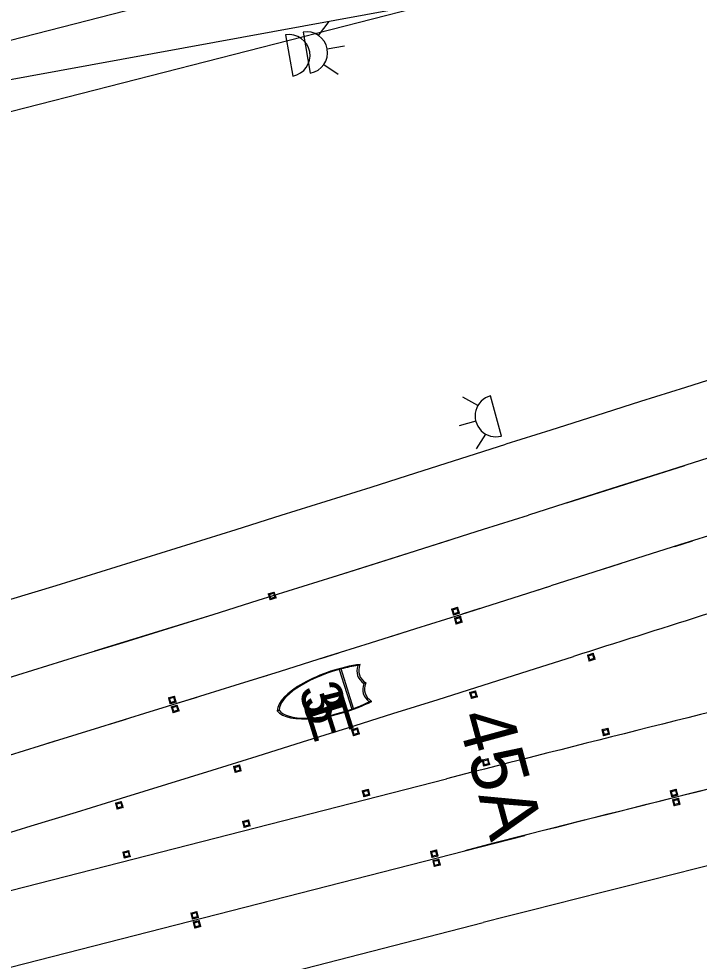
# Model space of a CAD drawing. Extents: x 2471014 to 2497726, y 6959577 to 6980268.
# Drawn here: x 2486252 to 2486362, y 6968251.5 to 6968403.9 of the extents above; entities that cross this region are included whole.
import ezdxf

# ---------------------------------------------------------------- set-up
doc = ezdxf.new("R2010")
doc.units = 0
for name, color, linetype in [('1', 7, 'Continuous'), ('13', 7, 'Continuous'), ('18', 7, 'Continuous'), ('23', 7, 'Continuous'), ('25', 7, 'Continuous'), ('5', 7, 'Continuous'), ('59', 7, 'Continuous'), ('C-ANNO-NOTE', 7, 'Continuous'), ('Level 40', 7, 'Continuous'), ('PMK_Del_D-SY_SZ_TYC_CTB', 7, 'Continuous'), ('PMK_Pav_Mark_Multi_Shield', 7, 'Continuous'), ('PMK_Pav_Mark_Wht_Number', 7, 'Continuous'), ('RDWY_PAVE_XSTREET_FOC', 7, 'Continuous'), ('S-BRDG-BENT', 7, 'Continuous'), ('SHADE SW', 7, 'Continuous'), ('V7_25', 7, 'Continuous')]:
    doc.layers.add(name, color=color, linetype=linetype)

msp = doc.modelspace()

# ---------------------------------------------------------------- linework, layer by layer
at = {"layer": '1'}
msp.add_line((2486324.14, 6968269.39), (2486333.83, 6968271.87), dxfattribs=at)
at = {"layer": '13'}
msp.add_line((2486190.43, 6968383.05), (2486361.16, 6968414.31), dxfattribs=at)
for centre, start, end in [((2488909.95, 6960235.84), 104.374936, 107.663843), ((2483751.61, 6976434.35), 284.374936, 287.663843)]:
    msp.add_arc(centre, 8500, start, end, dxfattribs=at)
at = {"layer": '18'}
msp.add_line((2485876.76, 6968142.35), (2486327.12, 6968257.77), dxfattribs=at)
msp.add_arc((2487750.43, 6962704.26), 5733, 101.840567, 104.374936, dxfattribs=at)
at = {"layer": '23'}
for p, q in [((2486292.36, 6968310.91), (2486293.33, 6968311.21)), ((2486292.57, 6968310.81), (2486292.36, 6968310.91)), ((2486292.36, 6968310.91), (2486292.44, 6968310.65)), ((2486292.44, 6968310.65), (2486292.66, 6968309.94)), ((2486292.77, 6968310.16), (2486292.57, 6968310.81)), ((2486293.33, 6968311.21), (2486293.21, 6968311.01)), ((2486293.21, 6968311.01), (2486293.26, 6968310.87)), ((2486293.26, 6968310.87), (2486293.42, 6968310.36)), ((2486293.63, 6968310.25), (2486293.33, 6968311.21)), ((2486293.63, 6968310.25), (2486292.66, 6968309.94)), ((2486292.66, 6968309.94), (2486292.77, 6968310.16)), ((2486293.42, 6968310.36), (2486293.63, 6968310.25)), ((2486322, 6968308.44), (2486322.97, 6968308.75)), ((2486322.21, 6968308.34), (2486322, 6968308.44)), ((2486322, 6968308.44), (2486322.08, 6968308.18)), ((2486322.08, 6968308.18), (2486322.31, 6968307.47)), ((2486322.41, 6968307.69), (2486322.21, 6968308.34)), ((2486323.27, 6968307.78), (2486322.31, 6968307.47)), ((2486322.31, 6968307.47), (2486322.41, 6968307.69)), ((2486322.97, 6968308.75), (2486322.86, 6968308.54)), ((2486322.86, 6968308.54), (2486322.9, 6968308.41)), ((2486322.9, 6968308.41), (2486323.06, 6968307.9)), ((2486323.27, 6968307.78), (2486322.97, 6968308.75)), ((2486323.06, 6968307.9), (2486323.27, 6968307.78)), ((2486322.46, 6968307), (2486323.43, 6968307.31)), ((2486322.67, 6968306.9), (2486322.46, 6968307)), ((2486322.46, 6968307), (2486322.55, 6968306.74)), ((2486322.55, 6968306.74), (2486322.77, 6968306.03)), ((2486322.88, 6968306.25), (2486322.67, 6968306.9)), ((2486323.74, 6968306.34), (2486322.77, 6968306.03)), ((2486322.77, 6968306.03), (2486322.88, 6968306.25)), ((2486323.43, 6968307.31), (2486323.32, 6968307.1)), ((2486323.32, 6968307.1), (2486323.36, 6968306.97)), ((2486323.36, 6968306.97), (2486323.52, 6968306.46)), ((2486323.74, 6968306.34), (2486323.43, 6968307.31)), ((2486323.52, 6968306.46), (2486323.74, 6968306.34)), ((2486343.96, 6968301), (2486344.92, 6968301.31)), ((2486344.17, 6968300.89), (2486343.96, 6968301)), ((2486343.96, 6968301), (2486344.26, 6968300.04)), ((2486344.33, 6968300.38), (2486344.17, 6968300.89)), ((2486345.23, 6968300.35), (2486344.26, 6968300.04)), ((2486344.26, 6968300.04), (2486344.38, 6968300.24)), ((2486344.38, 6968300.24), (2486344.33, 6968300.38)), ((2486344.92, 6968301.31), (2486344.82, 6968301.09)), ((2486344.82, 6968301.09), (2486345.02, 6968300.45)), ((2486345.15, 6968300.6), (2486344.92, 6968301.31)), ((2486345.02, 6968300.45), (2486345.23, 6968300.35)), ((2486345.23, 6968300.35), (2486345.15, 6968300.6)), ((2486324.89, 6968294.95), (2486325.86, 6968295.26)), ((2486325.86, 6968295.26), (2486325.75, 6968295.04)), ((2486326.09, 6968294.55), (2486325.86, 6968295.26)), ((2486276.2, 6968294.09), (2486277.17, 6968294.39)), ((2486276.41, 6968293.99), (2486276.2, 6968294.09)), ((2486276.2, 6968294.09), (2486276.28, 6968293.84)), ((2486276.28, 6968293.84), (2486276.5, 6968293.12)), ((2486276.61, 6968293.34), (2486276.41, 6968293.99)), ((2486277.17, 6968294.39), (2486277.05, 6968294.19)), ((2486277.05, 6968294.19), (2486277.1, 6968294.06)), ((2486277.1, 6968294.06), (2486277.25, 6968293.54)), ((2486277.47, 6968293.43), (2486277.17, 6968294.39)), ((2486325.11, 6968294.84), (2486324.89, 6968294.95)), ((2486324.89, 6968294.95), (2486325.2, 6968293.99)), ((2486325.27, 6968294.32), (2486325.11, 6968294.84)), ((2486326.17, 6968294.29), (2486325.2, 6968293.99)), ((2486325.2, 6968293.99), (2486325.31, 6968294.19)), ((2486325.31, 6968294.19), (2486325.27, 6968294.32)), ((2486325.75, 6968295.04), (2486325.96, 6968294.39)), ((2486325.96, 6968294.39), (2486326.17, 6968294.29)), ((2486326.17, 6968294.29), (2486326.09, 6968294.55)), ((2486277.47, 6968293.43), (2486276.5, 6968293.12)), ((2486276.5, 6968293.12), (2486276.61, 6968293.34)), ((2486276.66, 6968292.65), (2486277.63, 6968292.95)), ((2486276.87, 6968292.55), (2486276.66, 6968292.65)), ((2486276.66, 6968292.65), (2486276.74, 6968292.4)), ((2486276.74, 6968292.4), (2486276.96, 6968291.68)), ((2486277.07, 6968291.9), (2486276.87, 6968292.55)), ((2486277.25, 6968293.54), (2486277.47, 6968293.43)), ((2486277.63, 6968292.95), (2486277.52, 6968292.75)), ((2486277.52, 6968292.75), (2486277.56, 6968292.62)), ((2486277.56, 6968292.62), (2486277.72, 6968292.1)), ((2486277.93, 6968291.99), (2486277.63, 6968292.95)), ((2486277.93, 6968291.99), (2486276.96, 6968291.68)), ((2486276.96, 6968291.68), (2486277.07, 6968291.9)), ((2486277.72, 6968292.1), (2486277.93, 6968291.99)), ((2486305.82, 6968288.95), (2486306.79, 6968289.25)), ((2486306.79, 6968289.25), (2486306.68, 6968289.03)), ((2486307.01, 6968288.54), (2486306.79, 6968289.25)), ((2486346.33, 6968288.97), (2486347.31, 6968289.22)), ((2486347.31, 6968289.22), (2486347.19, 6968289)), ((2486347.49, 6968288.49), (2486347.31, 6968289.22)), ((2486306.03, 6968288.83), (2486305.82, 6968288.95)), ((2486305.82, 6968288.95), (2486306.12, 6968287.98)), ((2486306.19, 6968288.32), (2486306.03, 6968288.83)), ((2486307.09, 6968288.28), (2486306.12, 6968287.98)), ((2486306.12, 6968287.98), (2486306.24, 6968288.18)), ((2486306.24, 6968288.18), (2486306.19, 6968288.32)), ((2486306.68, 6968289.03), (2486306.88, 6968288.39)), ((2486306.88, 6968288.39), (2486307.09, 6968288.28)), ((2486307.09, 6968288.28), (2486307.01, 6968288.54)), ((2486346.53, 6968288.84), (2486346.33, 6968288.97)), ((2486346.33, 6968288.97), (2486346.57, 6968287.99)), ((2486346.67, 6968288.32), (2486346.53, 6968288.84)), ((2486347.56, 6968288.23), (2486346.57, 6968287.99)), ((2486346.57, 6968287.99), (2486346.7, 6968288.18)), ((2486346.7, 6968288.18), (2486346.67, 6968288.32)), ((2486347.19, 6968289), (2486347.36, 6968288.35)), ((2486347.36, 6968288.35), (2486347.56, 6968288.23)), ((2486347.56, 6968288.23), (2486347.49, 6968288.49)), ((2486286.73, 6968282.99), (2486287.7, 6968283.29)), ((2486287.7, 6968283.29), (2486287.59, 6968283.07)), ((2486287.59, 6968283.07), (2486287.79, 6968282.42)), ((2486287.92, 6968282.58), (2486287.7, 6968283.29)), ((2486326.94, 6968284.06), (2486327.92, 6968284.31)), ((2486327.15, 6968283.93), (2486326.94, 6968284.06)), ((2486326.94, 6968284.06), (2486327.19, 6968283.08)), ((2486327.28, 6968283.41), (2486327.15, 6968283.93)), ((2486328.17, 6968283.33), (2486327.19, 6968283.08)), ((2486327.19, 6968283.08), (2486327.31, 6968283.27)), ((2486327.31, 6968283.27), (2486327.28, 6968283.41)), ((2486327.92, 6968284.31), (2486327.8, 6968284.1)), ((2486327.8, 6968284.1), (2486327.97, 6968283.44)), ((2486328.1, 6968283.59), (2486327.92, 6968284.31)), ((2486327.97, 6968283.44), (2486328.17, 6968283.33)), ((2486328.17, 6968283.33), (2486328.1, 6968283.59)), ((2486286.94, 6968282.87), (2486286.73, 6968282.99)), ((2486286.73, 6968282.99), (2486287.03, 6968282.02)), ((2486287.1, 6968282.36), (2486286.94, 6968282.87)), ((2486288, 6968282.32), (2486287.03, 6968282.02)), ((2486287.03, 6968282.02), (2486287.14, 6968282.22)), ((2486287.14, 6968282.22), (2486287.1, 6968282.36)), ((2486287.79, 6968282.42), (2486288, 6968282.32)), ((2486288, 6968282.32), (2486287.92, 6968282.58)), ((2486307.56, 6968279.1), (2486308.55, 6968279.35)), ((2486307.77, 6968278.97), (2486307.56, 6968279.1)), ((2486307.56, 6968279.1), (2486307.81, 6968278.11)), ((2486307.9, 6968278.45), (2486307.77, 6968278.97)), ((2486308.55, 6968279.35), (2486308.43, 6968279.13)), ((2486308.43, 6968279.13), (2486308.6, 6968278.48)), ((2486308.73, 6968278.63), (2486308.55, 6968279.35)), ((2486308.8, 6968278.37), (2486308.73, 6968278.63)), ((2486357.36, 6968279.09), (2486358.34, 6968279.33)), ((2486357.56, 6968278.97), (2486357.36, 6968279.09)), ((2486357.36, 6968279.09), (2486357.42, 6968278.82)), ((2486357.42, 6968278.82), (2486357.6, 6968278.1)), ((2486357.72, 6968278.31), (2486357.56, 6968278.97)), ((2486358.34, 6968279.33), (2486358.22, 6968279.14)), ((2486358.22, 6968279.14), (2486358.25, 6968279)), ((2486358.25, 6968279), (2486358.38, 6968278.48)), ((2486358.59, 6968278.35), (2486358.34, 6968279.33)), ((2486267.63, 6968277.07), (2486268.59, 6968277.37)), ((2486267.84, 6968276.95), (2486267.63, 6968277.07)), ((2486267.63, 6968277.07), (2486267.92, 6968276.1)), ((2486268.59, 6968277.37), (2486268.49, 6968277.15)), ((2486268.49, 6968277.15), (2486268.69, 6968276.5)), ((2486268.81, 6968276.66), (2486268.59, 6968277.37)), ((2486308.8, 6968278.37), (2486307.81, 6968278.11)), ((2486307.81, 6968278.11), (2486307.94, 6968278.31)), ((2486307.94, 6968278.31), (2486307.9, 6968278.45)), ((2486308.6, 6968278.48), (2486308.8, 6968278.37)), ((2486358.59, 6968278.35), (2486357.6, 6968278.1)), ((2486357.6, 6968278.1), (2486357.72, 6968278.31)), ((2486357.73, 6968277.63), (2486358.72, 6968277.88)), ((2486357.93, 6968277.52), (2486357.73, 6968277.63)), ((2486357.73, 6968277.63), (2486357.8, 6968277.37)), ((2486357.8, 6968277.37), (2486357.98, 6968276.65)), ((2486358.1, 6968276.86), (2486357.93, 6968277.52)), ((2486358.38, 6968278.48), (2486358.59, 6968278.35)), ((2486358.72, 6968277.88), (2486358.59, 6968277.68)), ((2486358.59, 6968277.68), (2486358.62, 6968277.54)), ((2486358.62, 6968277.54), (2486358.75, 6968277.03)), ((2486358.96, 6968276.89), (2486358.72, 6968277.88)), ((2486358.75, 6968277.03), (2486358.96, 6968276.89)), ((2486268, 6968276.44), (2486267.84, 6968276.95)), ((2486268.89, 6968276.4), (2486267.92, 6968276.1)), ((2486267.92, 6968276.1), (2486268.04, 6968276.3)), ((2486268.04, 6968276.3), (2486268, 6968276.44)), ((2486268.69, 6968276.5), (2486268.89, 6968276.4)), ((2486268.89, 6968276.4), (2486268.81, 6968276.66)), ((2486358.96, 6968276.89), (2486357.98, 6968276.65)), ((2486357.98, 6968276.65), (2486358.1, 6968276.86)), ((2486288.19, 6968274.13), (2486289.17, 6968274.38)), ((2486288.4, 6968274), (2486288.19, 6968274.13)), ((2486288.19, 6968274.13), (2486288.44, 6968273.15)), ((2486288.53, 6968273.48), (2486288.4, 6968274)), ((2486289.17, 6968274.38), (2486289.05, 6968274.17)), ((2486289.05, 6968274.17), (2486289.22, 6968273.51)), ((2486289.36, 6968273.66), (2486289.17, 6968274.38)), ((2486289.42, 6968273.4), (2486288.44, 6968273.15)), ((2486288.44, 6968273.15), (2486288.57, 6968273.35)), ((2486288.57, 6968273.35), (2486288.53, 6968273.48)), ((2486289.22, 6968273.51), (2486289.42, 6968273.4)), ((2486289.42, 6968273.4), (2486289.36, 6968273.66)), ((2486268.82, 6968269.17), (2486269.8, 6968269.42)), ((2486269.8, 6968269.42), (2486269.68, 6968269.2)), ((2486269.98, 6968268.7), (2486269.8, 6968269.42)), ((2486318.58, 6968269.25), (2486319.57, 6968269.51)), ((2486319.57, 6968269.51), (2486319.44, 6968269.31)), ((2486319.82, 6968268.52), (2486319.57, 6968269.51)), ((2486269.02, 6968269.04), (2486268.82, 6968269.17)), ((2486268.82, 6968269.17), (2486269.07, 6968268.18)), ((2486269.16, 6968268.52), (2486269.02, 6968269.04)), ((2486270.05, 6968268.44), (2486269.07, 6968268.18)), ((2486269.07, 6968268.18), (2486269.19, 6968268.38)), ((2486269.19, 6968268.38), (2486269.16, 6968268.52)), ((2486269.68, 6968269.2), (2486269.85, 6968268.55)), ((2486269.85, 6968268.55), (2486270.05, 6968268.44)), ((2486270.05, 6968268.44), (2486269.98, 6968268.7)), ((2486318.78, 6968269.14), (2486318.58, 6968269.25)), ((2486318.58, 6968269.25), (2486318.65, 6968268.99)), ((2486318.65, 6968268.99), (2486318.83, 6968268.27)), ((2486318.95, 6968268.49), (2486318.78, 6968269.14)), ((2486319.82, 6968268.52), (2486318.83, 6968268.27)), ((2486318.83, 6968268.27), (2486318.95, 6968268.49)), ((2486318.95, 6968267.8), (2486319.94, 6968268.05)), ((2486319.44, 6968269.31), (2486319.48, 6968269.17)), ((2486319.48, 6968269.17), (2486319.61, 6968268.65)), ((2486319.61, 6968268.65), (2486319.82, 6968268.52)), ((2486319.94, 6968268.05), (2486319.81, 6968267.86)), ((2486319.81, 6968267.86), (2486319.85, 6968267.72)), ((2486320.19, 6968267.07), (2486319.94, 6968268.05)), ((2486319.16, 6968267.69), (2486318.95, 6968267.8)), ((2486318.95, 6968267.8), (2486319.02, 6968267.54)), ((2486319.02, 6968267.54), (2486319.21, 6968266.82)), ((2486319.32, 6968267.03), (2486319.16, 6968267.69)), ((2486320.19, 6968267.07), (2486319.21, 6968266.82)), ((2486319.21, 6968266.82), (2486319.32, 6968267.03)), ((2486319.85, 6968267.72), (2486319.98, 6968267.2)), ((2486319.98, 6968267.2), (2486320.19, 6968267.07)), ((2486279.83, 6968259.32), (2486280.82, 6968259.58)), ((2486280.04, 6968259.21), (2486279.83, 6968259.32)), ((2486279.83, 6968259.32), (2486279.9, 6968259.06)), ((2486279.9, 6968259.06), (2486280.09, 6968258.34)), ((2486280.2, 6968258.55), (2486280.04, 6968259.21)), ((2486280.82, 6968259.58), (2486280.69, 6968259.38)), ((2486280.69, 6968259.38), (2486280.73, 6968259.24)), ((2486280.73, 6968259.24), (2486280.86, 6968258.72)), ((2486281.07, 6968258.59), (2486280.82, 6968259.58)), ((2486280.86, 6968258.72), (2486281.07, 6968258.59)), ((2486281.07, 6968258.59), (2486280.09, 6968258.34)), ((2486280.09, 6968258.34), (2486280.2, 6968258.55)), ((2486280.21, 6968257.87), (2486281.19, 6968258.12)), ((2486280.41, 6968257.76), (2486280.21, 6968257.87)), ((2486280.21, 6968257.87), (2486280.27, 6968257.61)), ((2486280.27, 6968257.61), (2486280.46, 6968256.89)), ((2486280.58, 6968257.1), (2486280.41, 6968257.76)), ((2486281.19, 6968258.12), (2486281.06, 6968257.93)), ((2486281.06, 6968257.93), (2486281.1, 6968257.79)), ((2486281.1, 6968257.79), (2486281.23, 6968257.27)), ((2486281.44, 6968257.14), (2486281.19, 6968258.12)), ((2486281.23, 6968257.27), (2486281.44, 6968257.14)), ((2486281.44, 6968257.14), (2486280.46, 6968256.89)), ((2486280.46, 6968256.89), (2486280.58, 6968257.1))]:
    msp.add_line(p, q, dxfattribs=at)
for points in [[(2486292.57, 6968310.81), (2486293.21, 6968311.01), (2486293.42, 6968310.36), (2486292.77, 6968310.16)], [(2486322.21, 6968308.34), (2486322.86, 6968308.54), (2486323.06, 6968307.9), (2486322.41, 6968307.69)], [(2486322.67, 6968306.9), (2486323.32, 6968307.1), (2486323.52, 6968306.46), (2486322.88, 6968306.25)], [(2486345.02, 6968300.45), (2486344.38, 6968300.24), (2486344.17, 6968300.89), (2486344.82, 6968301.09)], [(2486276.41, 6968293.99), (2486277.05, 6968294.19), (2486277.25, 6968293.54), (2486276.61, 6968293.34)], [(2486325.96, 6968294.39), (2486325.31, 6968294.19), (2486325.11, 6968294.84), (2486325.75, 6968295.04)], [(2486276.87, 6968292.55), (2486277.52, 6968292.75), (2486277.72, 6968292.1), (2486277.07, 6968291.9)], [(2486306.88, 6968288.39), (2486306.24, 6968288.18), (2486306.03, 6968288.83), (2486306.68, 6968289.03)], [(2486347.36, 6968288.35), (2486346.7, 6968288.18), (2486346.53, 6968288.84), (2486347.19, 6968289)], [(2486287.79, 6968282.42), (2486287.14, 6968282.22), (2486286.94, 6968282.87), (2486287.59, 6968283.07)], [(2486327.97, 6968283.44), (2486327.31, 6968283.27), (2486327.15, 6968283.93), (2486327.8, 6968284.1)], [(2486308.6, 6968278.48), (2486307.94, 6968278.31), (2486307.77, 6968278.97), (2486308.43, 6968279.13)], [(2486357.56, 6968278.97), (2486358.22, 6968279.14), (2486358.38, 6968278.48), (2486357.72, 6968278.31)], [(2486268.69, 6968276.5), (2486268.04, 6968276.3), (2486267.84, 6968276.95), (2486268.49, 6968277.15)], [(2486357.93, 6968277.52), (2486358.59, 6968277.68), (2486358.75, 6968277.03), (2486358.1, 6968276.86)], [(2486289.22, 6968273.51), (2486288.57, 6968273.35), (2486288.4, 6968274), (2486289.05, 6968274.17)], [(2486269.85, 6968268.55), (2486269.19, 6968268.38), (2486269.02, 6968269.04), (2486269.68, 6968269.2)], [(2486318.78, 6968269.14), (2486319.44, 6968269.31), (2486319.61, 6968268.65), (2486318.95, 6968268.49)], [(2486319.16, 6968267.69), (2486319.81, 6968267.86), (2486319.98, 6968267.2), (2486319.32, 6968267.03)], [(2486280.04, 6968259.21), (2486280.69, 6968259.38), (2486280.86, 6968258.72), (2486280.2, 6968258.55)], [(2486280.41, 6968257.76), (2486281.06, 6968257.93), (2486281.23, 6968257.27), (2486280.58, 6968257.1)]]:
    msp.add_lwpolyline(points, close=True, dxfattribs=at)
at = {"layer": '25'}
msp.add_line((2485870.81, 6968165.59), (2486321.17, 6968281.02), dxfattribs=at)
for centre, radius, start, end in [((2488909.95, 6960235.84), 8464, 107.367847, 107.663843), ((2483751.61, 6976434.35), 8536, 284.374936, 287.663843), ((2487750.43, 6962704.26), 5757, 103.699749, 104.374936)]:
    msp.add_arc(centre, radius, start, end, dxfattribs=at)
at = {"layer": '5'}
msp.add_line((2485873.78, 6968153.97), (2486324.14, 6968269.39), dxfattribs=at)
for centre, radius, start, end in [((2479474.04, 6969335.88), 8460, 6.37617, 6.37617), ((2487750.43, 6962704.26), 5745, 103.688373, 104.374936)]:
    msp.add_arc(centre, radius, start, end, dxfattribs=at)
at = {"layer": '59'}
for centre, radius, start, end in [((2488909.95, 6960235.84), 8476, 104.517558, 107.663843), ((2483751.61, 6976434.35), 8524, 284.374936, 287.663843)]:
    msp.add_arc(centre, radius, start, end, dxfattribs=at)
at = {"layer": 'C-ANNO-NOTE'}
msp.add_arc((2487750.43, 6962704.26), 5745, 98.225813, 104.374936, dxfattribs=at)
at = {"layer": 'Level 40'}
for p, q in [((2486358.09, 6968318.58), (2486360.95, 6968319.48)), ((2486346.65, 6968314.96), (2486349.51, 6968315.86)), ((2486335.21, 6968311.32), (2486338.07, 6968312.23)), ((2486323.78, 6968307.69), (2486326.64, 6968308.6)), ((2486312.33, 6968304.08), (2486315.19, 6968304.98)), ((2486300.88, 6968300.48), (2486303.75, 6968301.38)), ((2486289.43, 6968296.9), (2486292.29, 6968297.8)), ((2486277.97, 6968293.34), (2486280.84, 6968294.23)), ((2486266.51, 6968289.79), (2486269.38, 6968290.67)), ((2486255.04, 6968286.26), (2486257.91, 6968287.14))]:
    msp.add_line(p, q, dxfattribs=at)
at = {"layer": 'PMK_Del_D-SY_SZ_TYC_CTB'}
for p, q in [((2486326.26, 6968341.37), (2486323.81, 6968342.74)), ((2486330.06, 6968336.42), (2486328.31, 6968342.94)), ((2486325.92, 6968338.81), (2486323.21, 6968338.08)), ((2486327.5, 6968336.76), (2486326, 6968334.38))]:
    msp.add_line(p, q, dxfattribs=at)
msp.add_arc((2486329.18, 6968339.68), 3.37, 104.997, 284.997, dxfattribs=at)
at = {"layer": 'PMK_Pav_Mark_Multi_Shield'}
for p, q in [((2486304.15, 6968298.78), (2486303.85, 6968298.7)), ((2486303.85, 6968298.7), (2486305.86, 6968292.28)), ((2486306.16, 6968292.39), (2486304.15, 6968298.78)), ((2486306.86, 6968299.34), (2486307.19, 6968299.51)), ((2486306.86, 6968299.34), (2486307.19, 6968299.51)), ((2486308.13, 6968296.52), (2486307.84, 6968296.43)), ((2486306.16, 6968292.39), (2486305.86, 6968292.28)), ((2486305.86, 6968292.28), (2486306.16, 6968292.39)), ((2486308.7, 6968293.48), (2486309.08, 6968293.53)), ((2486309.08, 6968293.53), (2486308.7, 6968293.48)), ((2486293.82, 6968292.03), (2486294.12, 6968292.12))]:
    msp.add_line(p, q, dxfattribs=at)
for centre, major_axis, start_param, end_param in [((2486304.03, 6968294.74), (10.14, 3.18), 1.138774, 3.023674), ((2486304.03, 6968294.74), (9.84, 3.09), 1.472354, 3.020104), ((2486304.03, 6968294.74), (9.84, 3.09), 1.164604, 1.442074), ((2486321.41, 6968302.34), (14.61, 4.59), 2.877224, 3.420954), ((2486321.4, 6968302.33), (14.31, 4.5), 2.857844, 3.425344), ((2486322.35, 6968299.34), (14.61, 4.59), 2.862234, 3.405964), ((2486322.34, 6968299.34), (14.31, 4.5), 2.857844, 3.425344), ((2486303.75, 6968295.63), (10.14, 3.18), 3.259514, 5.144414), ((2486303.75, 6968295.63), (9.84, 3.09), 3.263084, 4.810824), ((2486303.75, 6968295.63), (9.84, 3.09), 4.841111, 5.118585)]:
    msp.add_ellipse(centre, major_axis=major_axis, ratio=0.373432, start_param=start_param, end_param=end_param, dxfattribs=at)
at = {"layer": 'RDWY_PAVE_XSTREET_FOC'}
for p, q in [((2486340.65, 6968325.64), (2486359.72, 6968331.68)), ((2486302.52, 6968313.57), (2486321.59, 6968319.59)), ((2486264.33, 6968301.68), (2486283.43, 6968307.6))]:
    msp.add_line(p, q, dxfattribs=at)
at = {"layer": 'S-BRDG-BENT'}
msp.add_line((2485246.23, 6968131.47), (2487181.35, 6968627.42), dxfattribs=at)
msp.add_line((2485246.23, 6968131.47), (2487181.35, 6968627.42), dxfattribs=at)
at = {"layer": 'SHADE SW'}
for p, q in [((2486300.5, 6968401.18), (2486302.2, 6968403.43)), ((2486295.16, 6968401.27), (2486296.34, 6968394.62)), ((2486297.98, 6968401.74), (2486299.16, 6968395.09)), ((2486301.89, 6968399.01), (2486304.66, 6968399.5)), ((2486301.33, 6968396.48), (2486303.66, 6968394.91))]:
    msp.add_line(p, q, dxfattribs=at)
for centre in [(2486295.75, 6968397.95), (2486298.57, 6968398.42)]:
    msp.add_arc(centre, 3.37, 280.0662, 100.0662, dxfattribs=at)
at = {"layer": 'V7_25'}
msp.add_line((2485243.45, 6968142.32), (2487178.57, 6968638.27), dxfattribs=at)
for centre, radius, start, end in [((2488909.95, 6960235.84), 8488, 104.374936, 107.663843), ((2483751.61, 6976434.35), 8512, 284.374936, 287.663843)]:
    msp.add_arc(centre, radius, start, end, dxfattribs=at)

# ---------------------------------------------------------------- texts
at = {"layer": 'PMK_Pav_Mark_Multi_Shield'}
for s, p in [('3', (2486297.21, 6968295.49)), ('5', (2486297.7, 6968293.94)), ('E', (2486298.21, 6968292.31))]:
    msp.add_text(s, height=6.67, rotation=287.4422, dxfattribs=at).set_placement(p)
at = {"layer": 'PMK_Pav_Mark_Wht_Number'}
msp.add_text('45A', height=8.9, rotation=285.1809, dxfattribs=at).set_placement((2486322.83, 6968291.1))

doc.saveas('drawing.dxf')
